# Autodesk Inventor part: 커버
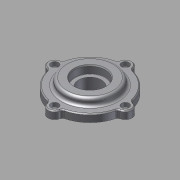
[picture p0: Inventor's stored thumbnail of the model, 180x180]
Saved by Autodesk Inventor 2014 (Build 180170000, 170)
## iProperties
Company: 한국ATC센터
Created: 2015-12
Part Number: 커버
Document SubType Name: Modeling
Designer: mdu
Density: 1 g/cm^3
Material: 일반
Appearance: 기본값
Author: mdu
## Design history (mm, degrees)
sketch "스케치1"
  geometry: C1 r 1.621 at (0, 6.75) reference; C2 r 1.621 at (-37, -30.25) reference; C3 r 1.621 at (0, -67.25) reference; C4 r 1.621 at (37, -30.25) reference; C5 r 10 at (0, -30.25) reference; C6 r 12 at (0, -30.25); C7 r 24.5 at (0, -30.25) reference; A1 r 3 centre (-38.77, -20.408) between (-38.239, -23.361) and (-35.862, -21.146) reference; A2 r 7 centre (-37, -30.25) between (-38.239, -23.361) and (-38.239, -37.139) reference; A3 r 3 centre (-38.77, -40.092) between (-35.862, -39.354) and (-38.239, -37.139) reference; A4 r 37 centre (0, -30.25) between (-35.862, -39.354) and (-9.104, -66.113) reference; A5 r 3 centre (-9.842, -69.02) between (-6.889, -68.489) and (-9.104, -66.113) reference; A6 r 7 centre (0, -67.25) between (-6.889, -68.489) and (6.889, -68.489) reference; A7 r 3 centre (9.842, -69.02) between (9.104, -66.112) and (6.889, -68.489) reference; A8 r 37 centre (0, -30.25) between (9.104, -66.112) and (35.863, -39.354) reference; A9 r 3 centre (38.77, -40.092) between (38.239, -37.139) and (35.863, -39.354) reference; A10 r 7 centre (37, -30.25) between (38.239, -37.139) and (38.239, -23.361) reference; A11 r 3 centre (38.77, -20.408) between (35.863, -21.146) and (38.239, -23.361) reference; A12 r 37 centre (0, -30.25) between (35.863, -21.146) and (9.104, 5.612) reference; A13 r 3 centre (9.842, 8.52) between (6.889, 7.989) and (9.104, 5.612) reference; A14 r 7 centre (0, 6.75) between (6.889, 7.989) and (-6.889, 7.989) reference; A15 r 3 centre (-9.842, 8.52) between (-9.104, 5.612) and (-6.889, 7.989) reference; A16 r 37 centre (0, -30.25) between (-9.104, 5.612) and (-35.862, -21.146) reference; 1 further point
  constraints: 1 centre point, 1 coincident
  dimensions: "d2" = 2 radial gap between concentric circles of C6 C5
extrude "돌출1" new body sketch "스케치1" distance "d0" = 8; taper "d1" = 0 deg
sketch "스케치2"
  geometry: C1 r 23.5 at (0, -30.25) reference; C2 r 12 at (0, -30.25) reference; 1 further point
extrude "돌출2" join sketch "스케치2" distance "d4" = 5; taper "d5" = 0 deg
sketch "스케치3"
  geometry: C1 r 23.5 at (0, 0) reference; C2 r 20.5 at (0, 0); 1 further point
  constraints: 1 centre point
  dimensions: "d6" = 3 radial gap between concentric circles of C2 C1
node "작업 평면1"
extrude "돌출3" join sketch "스케치3" stored distance "d7" = 5; taper "d8" = 0 deg
fillet "모깎기1" dims "d9" = 3
sketch "스케치4"
  geometry: C1 r 12 at (0, -30.25) reference; C2 r 27 at (0, -30.25); 1 further point
  constraints: 1 centre point
  dimensions: "d10" = 15 radial gap between concentric circles of C1 C2
extrude "돌출4" join sketch "스케치4" distance "d11" = 7; taper "d12" = 0 deg
fillet "모깎기2" dims "d13" = 3
chamfer "모따기1" distance "d14" = 1; stored, may be unused: second distance "d15" = 2, angle "d16" = 45 deg
node "작업점1"
  node "작업축1"
chamfer "모따기2" distance "d24" = 1; stored, may be unused: second distance "d25" = 2, angle "d26" = 45 deg
hole "구멍6" diameter "d43" = 4.5; stored, may be unused: countersink angle "d47" = 90 deg, drill point angle "d49" = 118 deg; dims "d41" = 10, "d42" = 10, "d44" = 6, "d45" = 8, "d46" = 4.4, "d48" = 8
sketch "스케치8"
  geometry: C1 r 12 at (0, 0) reference; C2 r 16 at (0, 0); 1 further point
  constraints: 1 centre point, 1 coincident
  dimensions: "d53" = 32 diameter of C2
extrude "돌출5" cut sketch "스케치8" distance "d54" = 8.3; taper "d55" = 0 deg
fillet "모깎기3" dims "d56" = 0.3
chamfer "모따기3" distance "d57" = 1.2; stored, may be unused: second distance "d58" = 2, angle "d59" = 30 deg
node "솔리드1"
pattern_circular "원형 패턴1" dims angle "d51" = 360 deg
node "참조1"
node "참조2"
